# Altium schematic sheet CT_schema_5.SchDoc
size 520 x 457 mm
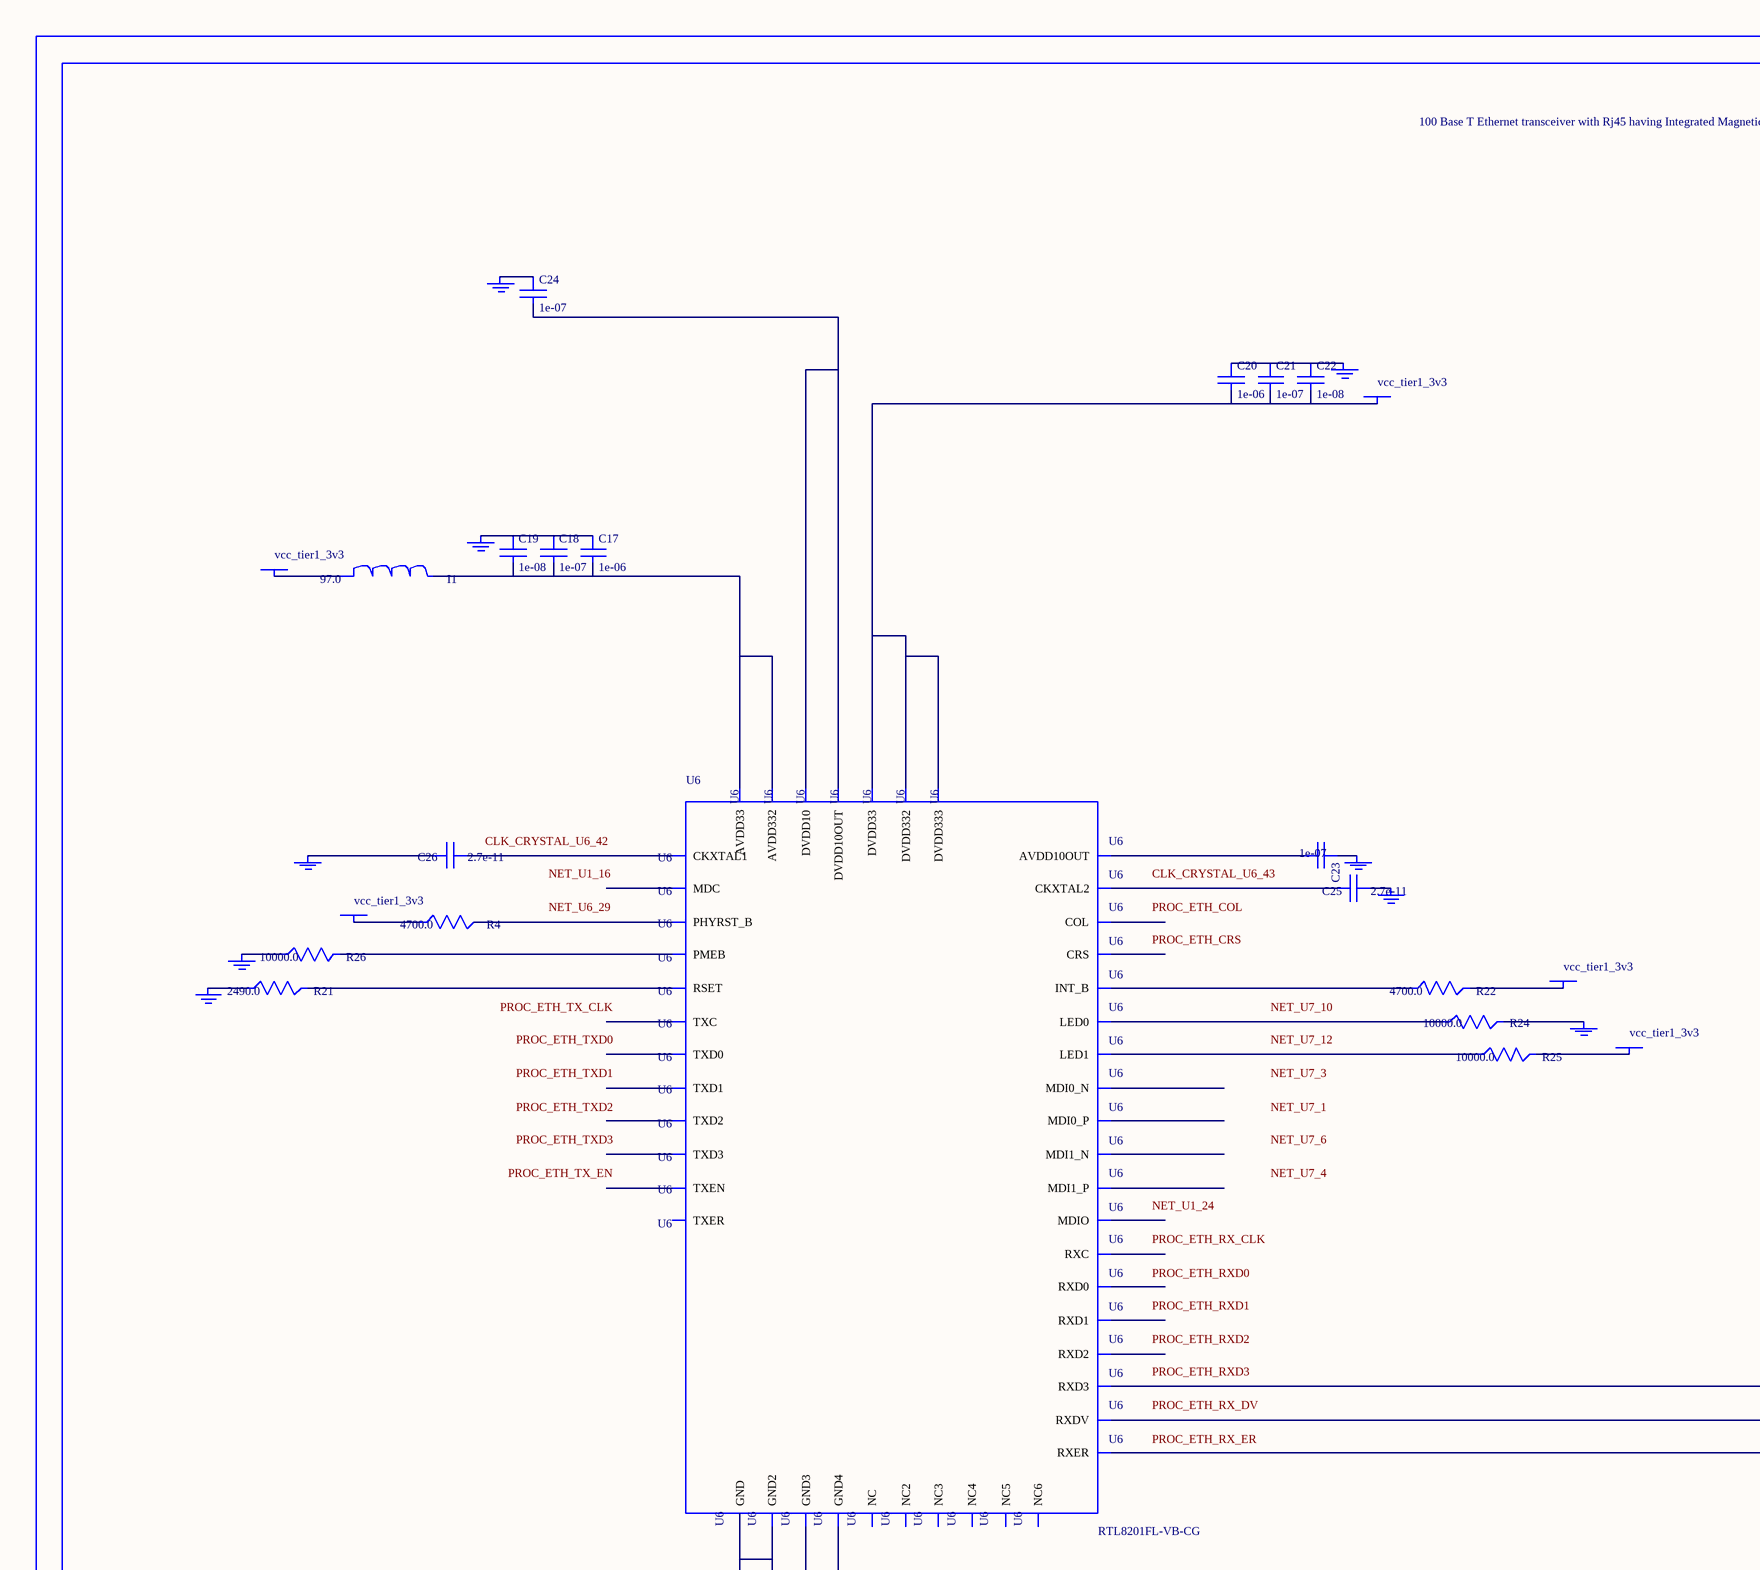
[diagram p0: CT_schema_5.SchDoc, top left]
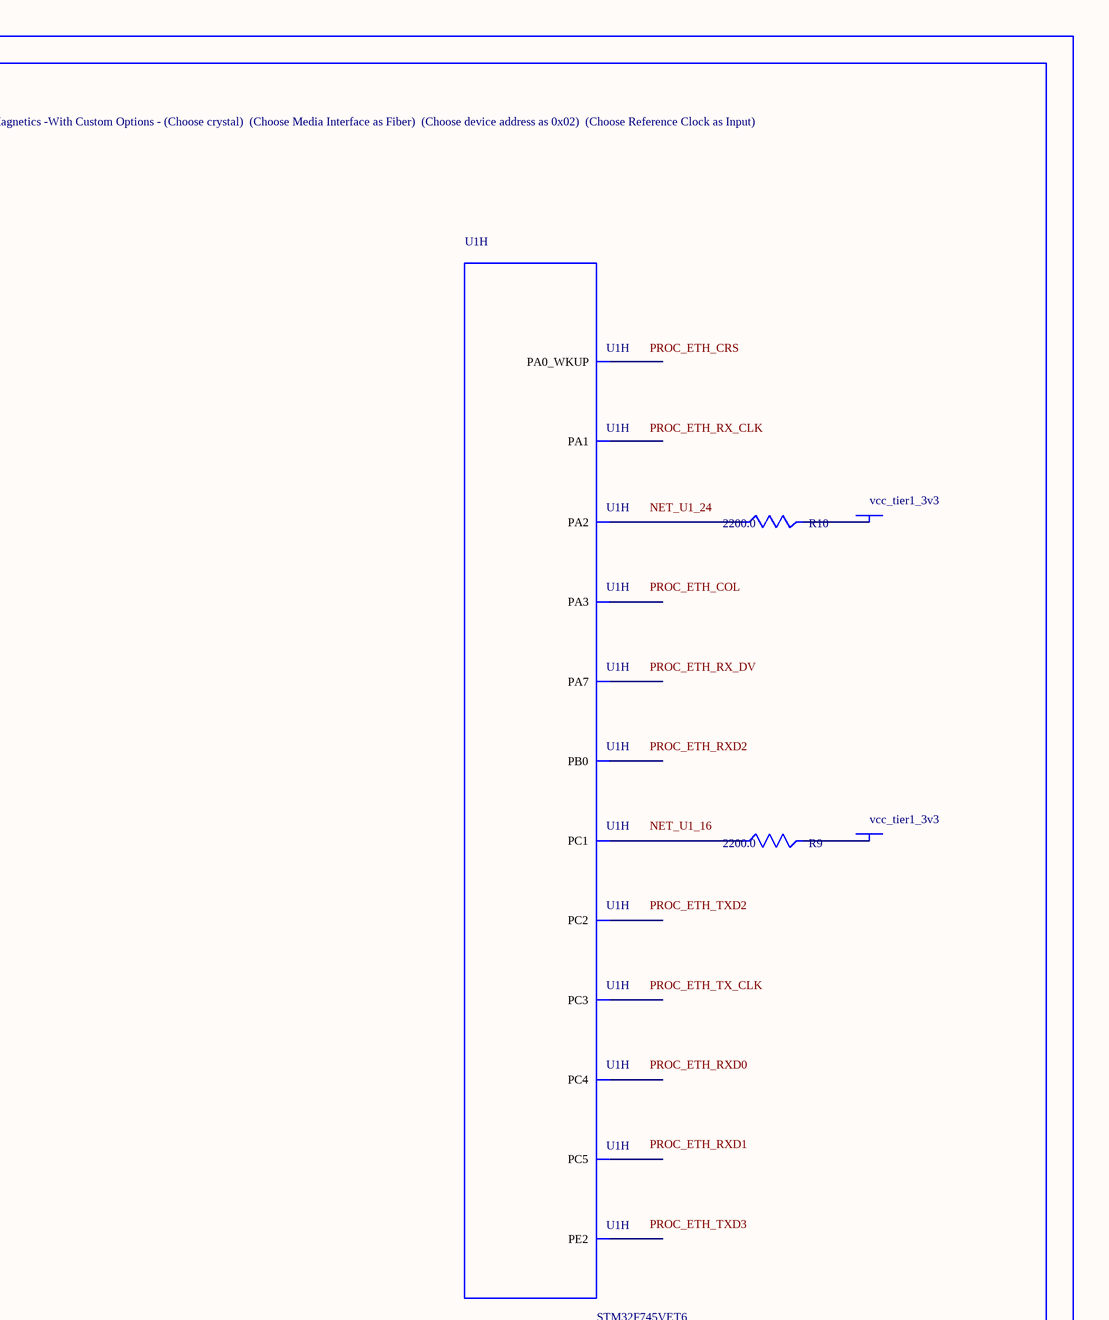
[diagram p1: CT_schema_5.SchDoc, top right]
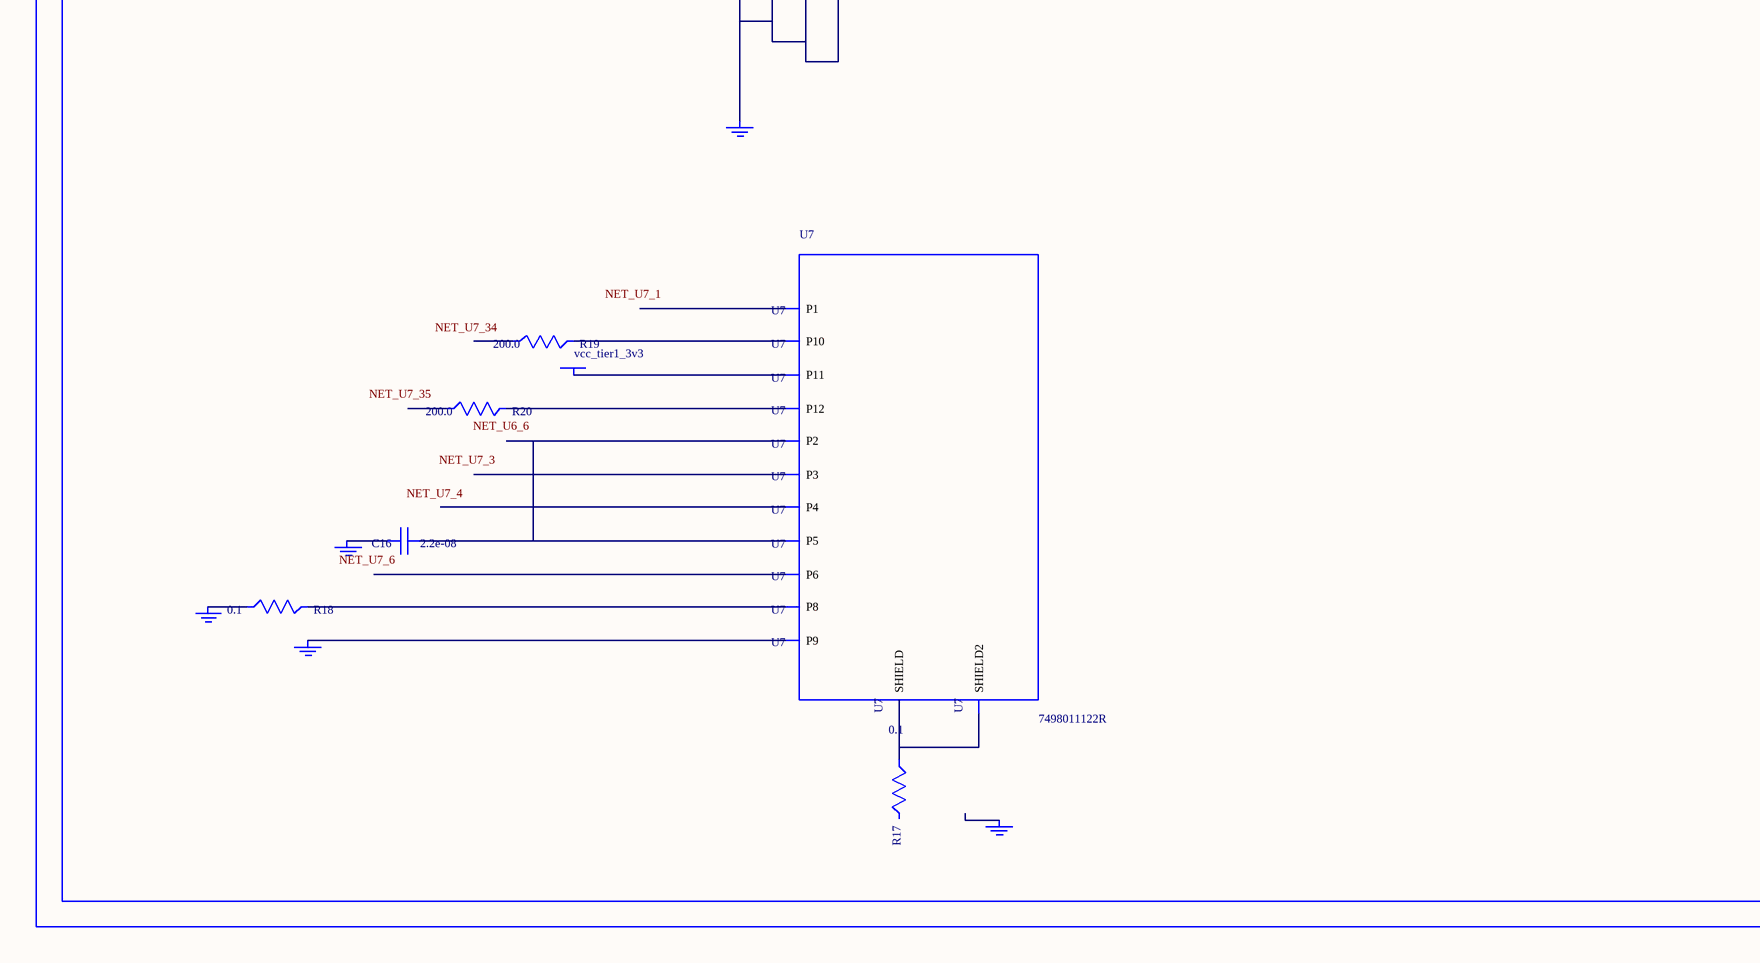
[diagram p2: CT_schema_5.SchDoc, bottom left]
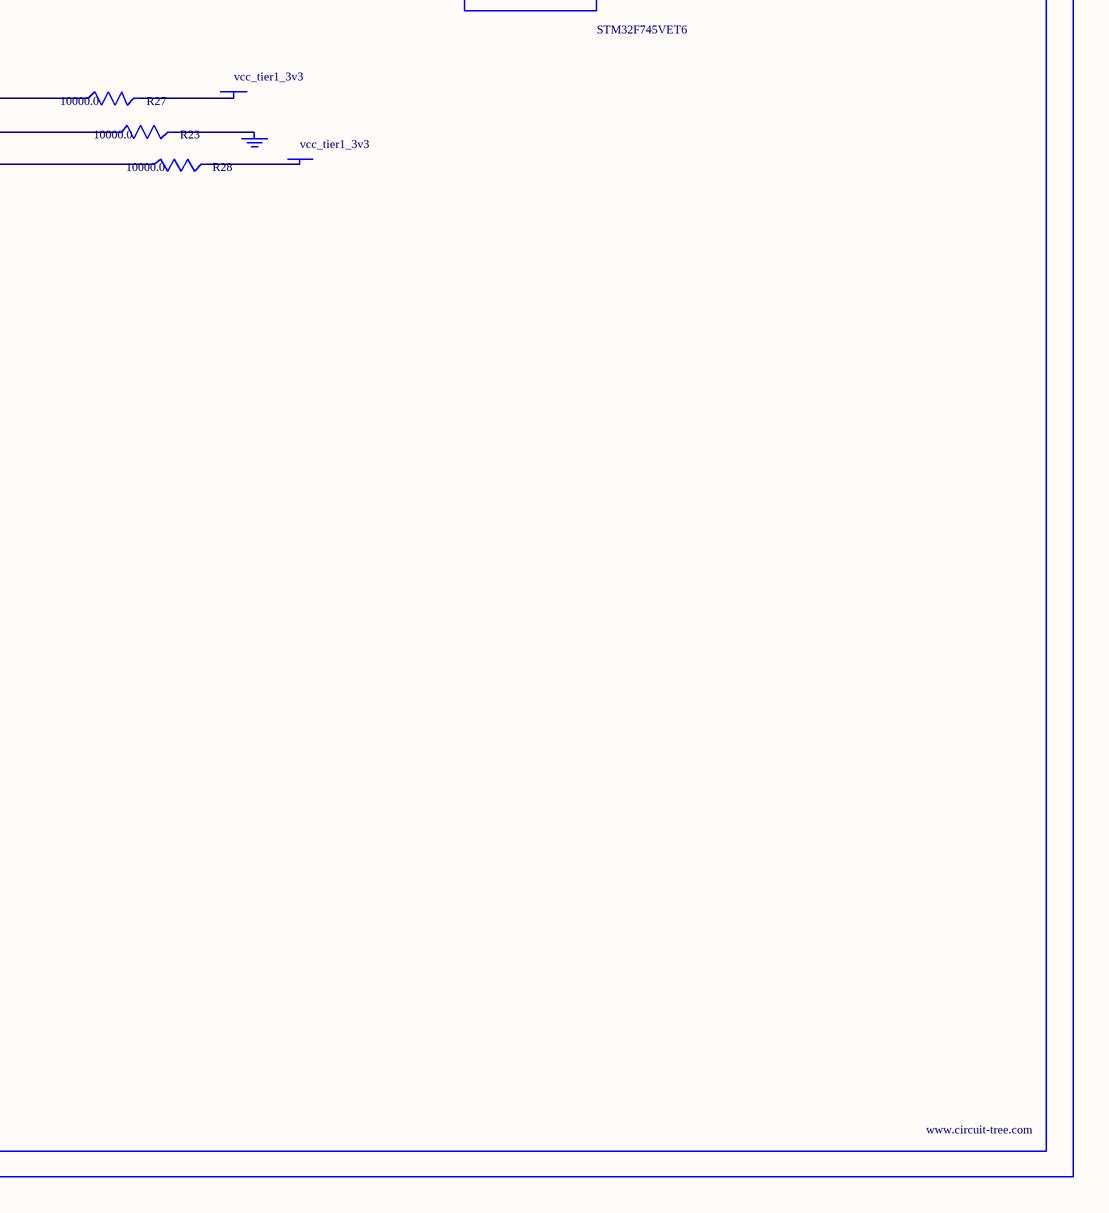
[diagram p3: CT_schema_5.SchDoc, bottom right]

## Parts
BORDER4  (no value)
C16  2.2e-08  [C0402]
C17  1e-06  [C0603]
C18  1e-07  [C0402]
C19  1e-08  [C0402]
C20  1e-06  [C0603]
C21  1e-07  [C0402]
C22  1e-08  [C0402]
C23  1e-07  [C0402]
C24  1e-07  [C0402]
C25  2.7e-11  [C0402]
C26  2.7e-11  [C0402]
GND_INSTANCE_4_0  (no value)
GND_INSTANCE_4_1  (no value)
GND_INSTANCE_4_2  (no value)
GND_INSTANCE_4_3  (no value)
GND_INSTANCE_4_4  (no value)
GND_INSTANCE_4_5  (no value)
GND_INSTANCE_4_6  (no value)
GND_INSTANCE_4_7  (no value)
GND_INSTANCE_4_8  (no value)
GND_INSTANCE_4_9  (no value)
GND_INSTANCE_4_10  (no value)
GND_INSTANCE_4_11  (no value)
GND_INSTANCE_4_12  (no value)
GND_INSTANCE_4_13  (no value)
GND_INSTANCE_4_14  (no value)
I1  97.0  [R0603]
POWER_INSTANCE_4_0  vcc_tier1_3v3
POWER_INSTANCE_4_1  vcc_tier1_3v3
POWER_INSTANCE_4_2  vcc_tier1_3v3
POWER_INSTANCE_4_3  vcc_tier1_3v3
POWER_INSTANCE_4_4  vcc_tier1_3v3
POWER_INSTANCE_4_5  vcc_tier1_3v3
POWER_INSTANCE_4_6  vcc_tier1_3v3
POWER_INSTANCE_4_7  vcc_tier1_3v3
POWER_INSTANCE_4_8  vcc_tier1_3v3
POWER_INSTANCE_4_9  vcc_tier1_3v3
R4  4700.0  [R0603]
R9  2200.0  [R0603]
R10  2200.0  [R0603]
R17  0.1  [R0603]
R18  0.1  [R0603]
R19  200.0  [R0603]
R20  200.0  [R0603]
R21  2490.0  [R0603]
R22  4700.0  [R0603]
R23  10000.0  [R0603]
R24  10000.0  [R0603]
R25  10000.0  [R0603]
R26  10000.0  [R0603]
R27  10000.0  [R0603]
R28  10000.0  [R0603]
U1  STM32F745VET6  [LQFP100]  (part H of 9)
U6  RTL8201FL-VB-CG  [RTL8201FL-VB-CG]
U7  7498011122R  [7498011122R]

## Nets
NetC16_1: C16.1 U7.2(P2) U7.5(P5)
NetC16_2: C16.2 GND_INSTANCE_4_11.0(GND)
NetC17_1: C17.1 C18.1 C19.1 GND_INSTANCE_4_0.0(GND)
NetC17_2: C17.2 C18.2 C19.2 I1.2 U6.6(AVDD33) U6.41(AVDD332)
NetC20_1: C20.1 C21.1 C22.1 GND_INSTANCE_4_3.0(GND)
NetC20_2: C20.2 C21.2 C22.2 POWER_INSTANCE_4_1.0(PWR) U6.15(DVDD33) U6.21(DVDD332) U6.37(DVDD333)
NetC23_1: C23.1 GND_INSTANCE_4_9.0(GND)
NetC23_2: C23.2 U6.48(AVDD10OUT)
NetC24_1: C24.1 GND_INSTANCE_4_5.0(GND)
NetC24_2: C24.2 U6.28(DVDD10) U6.40(DVDD10OUT)
NetC25_1: C25.1 GND_INSTANCE_4_7.0(GND)
NetC25_2: C25.2 U6.43(CKXTAL2)
NetC26_1: C26.1 U6.42(CKXTAL1)
NetC26_2: C26.2 GND_INSTANCE_4_6.0(GND)
NetGND_INSTANCE_4_1_0: GND_INSTANCE_4_1.0(GND) R26.1
NetGND_INSTANCE_4_2_0: GND_INSTANCE_4_2.0(GND) R23.2
NetGND_INSTANCE_4_4_0: GND_INSTANCE_4_4.0(GND) R24.2
NetGND_INSTANCE_4_8_0: GND_INSTANCE_4_8.0(GND) R21.1
NetGND_INSTANCE_4_10_0: GND_INSTANCE_4_10.0(GND) U6.7(GND) U6.20(GND2) U6.33(GND3) U6.47(GND4)
NetGND_INSTANCE_4_12_0: GND_INSTANCE_4_12.0(GND) R18.1
NetGND_INSTANCE_4_13_0: GND_INSTANCE_4_13.0(GND) U7.9(P9)
NetI1_1: I1.1 POWER_INSTANCE_4_0.0(PWR)
NetPOWER_INSTANCE_4_2_0: POWER_INSTANCE_4_2.0(PWR) R27.2
NetPOWER_INSTANCE_4_3_0: POWER_INSTANCE_4_3.0(PWR) R22.2
NetPOWER_INSTANCE_4_4_0: POWER_INSTANCE_4_4.0(PWR) R25.2
NetPOWER_INSTANCE_4_5_0: POWER_INSTANCE_4_5.0(PWR) R28.2
NetPOWER_INSTANCE_4_6_0: POWER_INSTANCE_4_6.0(PWR) R4.1
NetPOWER_INSTANCE_4_7_0: POWER_INSTANCE_4_7.0(PWR) R9.2
NetPOWER_INSTANCE_4_8_0: POWER_INSTANCE_4_8.0(PWR) R10.2
NetPOWER_INSTANCE_4_9_0: POWER_INSTANCE_4_9.0(PWR) U7.11(P11)
NetR4_2: R4.2 U6.29(PHYRST_B)
NetR9_1: R9.1 U1.16(PC1)
NetR10_1: R10.1 U1.24(PA2)
NetR17_1: R17.1 U7.13(SHIELD) U7.14(SHIELD2)
NetR18_2: R18.2 U7.8(P8)
NetR19_2: R19.2 U7.10(P10)
NetR20_2: R20.2 U7.12(P12)
NetR21_2: R21.2 U6.46(RSET)
NetR22_1: R22.1 U6.32(INT_B)
NetR23_1: R23.1 U6.13(RXDV)
NetR24_1: R24.1 U6.34(LED0)
NetR25_1: R25.1 U6.35(LED1)
NetR26_2: R26.2 U6.10(PMEB)
NetR27_1: R27.1 U6.18(RXD3)
NetR28_1: R28.1 U6.39(RXER)

Not connected (* = marked no-connect by the designer): GND_INSTANCE_4_14 0(GND); R17 2; R19 1; R20 1; U1 1(PE2) 17(PC2) 18(PC3) 22(PA0_WKUP) 23(PA1) 25(PA3) 31(PA7) 32(PC4) 33(PC5) 34(PB0); U6 1(MDI0_P) 2(MDI0_N) 3(NC) 4(MDI1_P) 5(MDI1_N) 8(NC2) 9(NC3) 11(NC4) 12(TXER) 14(RXD0) 16(RXD1) 17(RXD2) 19(RXC) 22(TXC) 23(TXD0) 24(TXD1) 25(TXD2) 26(TXD3) 27(TXEN) 30(MDC) 31(MDIO) 36(CRS) 38(COL) 44(NC5) 45(NC6); U7 1(P1) 3(P3) 4(P4) 6(P6)

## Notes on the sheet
- Labels drawn without touching a wire or pin: CLK_CRYSTAL_U6_42, CLK_CRYSTAL_U6_43, NET_U1_16, NET_U1_24, NET_U6_6, NET_U6_29, NET_U7_1, NET_U7_3, NET_U7_4, NET_U7_6, NET_U7_10, NET_U7_12, NET_U7_34, NET_U7_35, PROC_ETH_COL, PROC_ETH_CRS, PROC_ETH_RX_CLK, PROC_ETH_RX_DV, PROC_ETH_RX_ER, PROC_ETH_RXD0, PROC_ETH_RXD1, PROC_ETH_RXD2, PROC_ETH_RXD3, PROC_ETH_TX_CLK, PROC_ETH_TX_EN, PROC_ETH_TXD0, PROC_ETH_TXD1, PROC_ETH_TXD2, PROC_ETH_TXD3

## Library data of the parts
BORDER4 = BORDER_PAGE4
C16 = C0402C223K3RAC
C17 C20 = C0603C105K3RACTU
C18 C21 C23 C24 = C0402C104K3RACTU
C19 C22 = C0402C103K3RAC
C25 C26 = C0402C270K3RAC
GND_INSTANCE_4_0-GND_INSTANCE_4_14 = GND
I1 = I1
POWER_INSTANCE_4_0-POWER_INSTANCE_4_9 = PWR
R4 R22 = RC0603JR-074K7L
R9 R10 = RC0603JR-072K2L
R17 R18 = ERJ-3RSFR10V
R19 R20 = RC0603JR-07200RL
R21 = ERA-3AED2490V
R23-R28 = RC0603JR-0710KL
